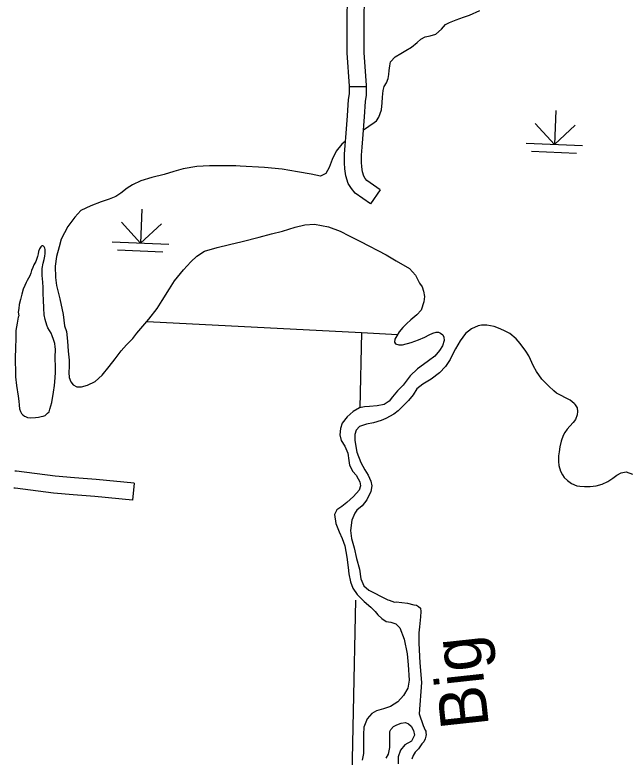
# Model space of a CAD drawing. Extents: x 1196286 to 1268366, y 2040822 to 2082115.
# Drawn here: x 1233530 to 1235560, y 2051997 to 2054453 of the extents above; entities that cross this region are included whole.
import ezdxf

# ---------------------------------------------------------------- set-up
doc = ezdxf.new("R2010")
doc.units = 0
for name, color, linetype in [('60', 7, 'Continuous'), ('62', 7, 'Continuous'), ('Level 69', 7, 'Continuous'), ('Level 73', 7, 'Continuous'), ('Level 74', 7, 'Continuous'), ('Level 86', 7, 'Continuous')]:
    doc.layers.add(name, color=color, linetype=linetype)

msp = doc.modelspace()

# ---------------------------------------------------------------- linework, layer by layer
at = {"layer": '60'}
for points in [[(1234677.4, 2053402.1), (1234672, 2053153)], [(1234658.3, 2052516.7), (1234634.4, 2051411.2)]]:
    msp.add_lwpolyline(points, dxfattribs=at)
at = {"layer": '62'}
for points in [[(1233540.8, 2053452.4), (1233537.6, 2053432.5), (1233533.5, 2053408.9), (1233533.5, 2053380.3), (1233532, 2053353.6), (1233530.8, 2053314.5), (1233531.3, 2053302.5), (1233531.8, 2053278.4), (1233531.8, 2053255.5), (1233535.2, 2053226.9), (1233540.7, 2053191.8), (1233543.5, 2053174.5), (1233544.4, 2053161.3), (1233546.1, 2053149.6), (1233549, 2053140.9), (1233552.7, 2053134.5), (1233556.3, 2053129.2), (1233562.3, 2053125.3), (1233565.3, 2053124.1), (1233572, 2053120.7), (1233580.6, 2053119.4), (1233598.9, 2053120.3), (1233608.3, 2053121.3), (1233617, 2053123.8), (1233623.7, 2053125.2), (1233630.5, 2053127.4), (1233638.8, 2053134.8), (1233643.4, 2053139.6), (1233646.1, 2053148.6), (1233652.4, 2053169.9), (1233657.8, 2053204.5), (1233661.4, 2053226.2), (1233664, 2053252.5), (1233664.7, 2053271.3), (1233664.5, 2053290.5), (1233663.4, 2053315), (1233663.9, 2053328.9), (1233664.4, 2053337.5), (1233664.5, 2053346.5), (1233663.9, 2053354.1), (1233662.6, 2053366.1), (1233658.6, 2053379.3), (1233653.5, 2053391.1), (1233650.3, 2053400.1), (1233639.3, 2053417.6), (1233636, 2053425.9), (1233631, 2053444.8), (1233627.1, 2053460.2), (1233626.3, 2053482.4), (1233624.8, 2053510.3), (1233623.9, 2053529.5), (1233623.9, 2053550.5), (1233623, 2053569), (1233620.7, 2053591.2), (1233621, 2053613.7), (1233624.2, 2053631.8), (1233627, 2053643.8), (1233629.4, 2053655), (1233630.3, 2053663.6), (1233630.7, 2053670.8), (1233630.4, 2053677.2), (1233629.4, 2053681.3), (1233626.8, 2053685.5), (1233625.3, 2053687.4), (1233623.1, 2053688.6), (1233621.6, 2053689.3), (1233619.4, 2053688.6), (1233615.9, 2053685.6), (1233611.7, 2053678.6), (1233609, 2053669.9), (1233607, 2053662.5), (1233605, 2053653.1), (1233603.1, 2053646.7), (1233599.6, 2053637.4), (1233593.4, 2053625.8), (1233589.2, 2053616.8), (1233585.7, 2053606.7), (1233582.9, 2053598.1), (1233579.8, 2053589.9), (1233571, 2053574.6), (1233567.9, 2053567.9), (1233562.9, 2053557.8), (1233557.5, 2053545.4), (1233552.8, 2053529), (1233548.4, 2053511.7), (1233544.8, 2053495.2), (1233543.1, 2053481), (1233541.7, 2053469.7), (1233542.9, 2053457.3), (1233540.8, 2053452.4)], [(1235381.5, 2053167.4), (1235368.6, 2053178.1), (1235323.5, 2053201.3), (1235314.6, 2053208.6), (1235297.2, 2053224.6), (1235274.7, 2053247.1), (1235257.4, 2053272.6), (1235247.5, 2053290.7), (1235231.9, 2053324.8), (1235222, 2053340.7), (1235202.8, 2053365.1), (1235190, 2053381), (1235168.1, 2053399), (1235153.6, 2053406.4), (1235136.5, 2053413.7), (1235117.1, 2053421.9), (1235092.4, 2053426), (1235074.8, 2053425.9), (1235063.9, 2053424.2), (1235041.3, 2053414.7), (1235021.6, 2053399.2), (1235003.7, 2053374.6), (1234988.7, 2053348.5), (1234978, 2053327.2), (1234970.6, 2053313), (1234955.7, 2053289.5), (1234936, 2053269.1), (1234908.3, 2053248.1), (1234880.8, 2053230.8), (1234861.1, 2053215.6), (1234848.1, 2053195.5), (1234833.6, 2053177.3), (1234812.3, 2053155.8), (1234798.7, 2053142.4), (1234785, 2053131.7), (1234758.2, 2053117.8), (1234742.4, 2053111.2), (1234717.2, 2053103.3), (1234694.7, 2053098.3), (1234671.3, 2053090.8), (1234660.3, 2053079.3), (1234655.3, 2053065), (1234655.4, 2053045.1), (1234662, 2053006.3), (1234675, 2052971.9), (1234688.5, 2052947.6), (1234699.9, 2052929.4), (1234708.6, 2052910.5), (1234712.1, 2052895), (1234708.5, 2052875.5), (1234695.4, 2052848.3), (1234679.8, 2052828.5), (1234662.7, 2052813.7), (1234655.1, 2052803.7), (1234645.8, 2052781.3), (1234641.2, 2052746.3), (1234644.6, 2052720.4), (1234653.9, 2052689.4), (1234660.9, 2052653.6), (1234670.6, 2052618.5), (1234675, 2052586.8), (1234685.6, 2052563.3), (1234701.8, 2052549.2), (1234720.1, 2052540.7), (1234742.8, 2052528), (1234764.3, 2052517.5), (1234769.6, 2052515.9), (1234786.7, 2052510), (1234792.7, 2052511.1), (1234829.4, 2052506.8), (1234850.7, 2052501.3), (1234859.2, 2052499.6), (1234866.7, 2052495.4), (1234872.6, 2052490.1), (1234873.9, 2052478.8), (1234872.6, 2052461.5), (1234869.1, 2052428.4), (1234867.7, 2052407.8), (1234866.9, 2052373.6), (1234870.9, 2052308.4), (1234876, 2052243.3), (1234868.2, 2052140.4), (1234882.3, 2052101.8), (1234888.9, 2052086), (1234890.7, 2052082.2), (1234891, 2052077.6), (1234891.3, 2052071.6), (1234890.5, 2052066.4), (1234888.8, 2052057.4), (1234884.2, 2052047.7), (1234877.8, 2052040.2), (1234866.3, 2052024.6), (1234855.7, 2052013.1), (1234848.8, 2052001.9), (1234843.7, 2051990.3)], [(1235381.5, 2053167.4), (1235385.1, 2053163), (1235391.5, 2053152.6), (1235392.5, 2053141.1), (1235391.9, 2053129.8), (1235386, 2053114.5), (1235378.7, 2053104.1), (1235367.6, 2053091.9), (1235358.4, 2053081.9), (1235350.3, 2053071.2), (1235345.2, 2053061.1), (1235338.9, 2053042.8), (1235334.4, 2053023.4), (1235331.8, 2053007.2), (1235329.7, 2052993.7), (1235329.7, 2052974.9), (1235330.9, 2052962.1), (1235336.5, 2052943.2), (1235342.7, 2052931), (1235348.5, 2052921.9), (1235359.2, 2052912.3), (1235372.8, 2052901.8), (1235389.9, 2052894.7), (1235400.8, 2052893), (1235415.4, 2052892), (1235434.5, 2052892.7), (1235454.8, 2052894.5), (1235474.4, 2052900.5), (1235492.9, 2052908.8), (1235509.2, 2052920.2), (1235522.9, 2052930), (1235537.3, 2052938), (1235553.5, 2052941.1), (1235574.3, 2052932.8)]]:
    msp.add_lwpolyline(points, dxfattribs=at)
at = {"layer": 'Level 69'}
for p, q in [((1234693.8, 2054215.6), (1234637.5, 2054214.9)), ((1234739.9, 2053874), (1234707.3, 2053828.2)), ((1233925.3, 2052903.5), (1233920, 2052847.5))]:
    msp.add_line(p, q, dxfattribs=at)
for points in [[(1234630.5, 2054413.1), (1234631.3, 2054535.2), (1234629.9, 2054610.4)], [(1234686.8, 2054412.8), (1234687.6, 2054535.5), (1234686.1, 2054611.5)], [(1234637.5, 2054214.9), (1234637.5, 2054217.1), (1234630, 2054327.3), (1234630.5, 2054413.1)], [(1234693.8, 2054215.6), (1234693.7, 2054219.4), (1234686.3, 2054329), (1234686.8, 2054412.8)], [(1234623.7, 2054020.6), (1234626.3, 2054047.5), (1234631.7, 2054119.5), (1234635.1, 2054172.7), (1234637.8, 2054191.5), (1234637.5, 2054214.9)], [(1234679.7, 2054015.2), (1234682.3, 2054042.6), (1234687.8, 2054115.6), (1234691.1, 2054166.9), (1234694.1, 2054187.8), (1234693.8, 2054215.6)], [(1234707.3, 2053828.2), (1234657.2, 2053863.7), (1234644.9, 2053878.5), (1234633.8, 2053895.7), (1234626, 2053920.9), (1234622.4, 2053943.8), (1234621, 2053964), (1234620.9, 2053991.9), (1234623.7, 2054020.6)], [(1234739.9, 2053874), (1234695.8, 2053905.3), (1234690.3, 2053911.9), (1234685.3, 2053919.7), (1234680.9, 2053933.8), (1234678.3, 2053950.1), (1234677.2, 2053966), (1234677.2, 2053989.3), (1234679.7, 2054015.2)], [(1233727.8, 2052921.4), (1233663.7, 2052926.7), (1233535.7, 2052943.2), (1233530.2, 2052943.5)], [(1233925.3, 2052903.5), (1233799.8, 2052915.4), (1233727.8, 2052921.4)], [(1233723.1, 2052865.3), (1233657.8, 2052870.7), (1233530.7, 2052887.1), (1233527.3, 2052887.3)], [(1233920, 2052847.5), (1233794.8, 2052859.4), (1233723.1, 2052865.3)]]:
    msp.add_lwpolyline(points, dxfattribs=at)
at = {"layer": 'Level 73'}
for p, q in [((1235320.8, 2054137.1), (1235316, 2054024.7)), ((1235316, 2054024.7), (1235252.6, 2054093.8)), ((1235316, 2054024.7), (1235385.1, 2054088.1)), ((1235222.3, 2054028.7), (1235409.7, 2054020.7)), ((1235240, 2054002.4), (1235389.8, 2053996)), ((1233951, 2053810.4), (1233946.2, 2053698)), ((1233946.2, 2053698), (1233882.8, 2053767.1)), ((1233946.2, 2053698), (1234015.3, 2053761.4)), ((1233852.5, 2053702.1), (1234039.9, 2053694)), ((1233870.2, 2053675.7), (1234020, 2053669.3))]:
    msp.add_line(p, q, dxfattribs=at)
at = {"layer": 'Level 74'}
for points in [[(1234684.6, 2054072.9), (1234719.6, 2054096.9), (1234726.8, 2054103.1), (1234735.3, 2054114.6), (1234743.6, 2054139.3), (1234746.3, 2054162.5), (1234747.5, 2054181.3), (1234749.8, 2054203.5), (1234753, 2054216.2), (1234760.8, 2054228.8), (1234766.3, 2054243), (1234768.1, 2054256.1), (1234768.7, 2054269.3), (1234770.9, 2054285), (1234774.1, 2054297.8), (1234789.4, 2054314.8), (1234807.7, 2054325.7), (1234824.3, 2054335.1), (1234842.9, 2054346), (1234862, 2054361.4), (1234873.8, 2054372.5), (1234888.2, 2054380.5), (1234905.1, 2054383.9), (1234923.2, 2054389.9), (1234941.9, 2054406.5), (1234955.7, 2054421.6), (1234968.6, 2054428.5), (1234990.9, 2054436.4), (1235015, 2054445.3), (1235035.4, 2054452.4), (1235069.8, 2054467.9)], [(1234625.1, 2054035.1), (1234612.8, 2054025.7), (1234594.2, 2054002.6), (1234580.7, 2053974.2), (1234571, 2053948.4), (1234559.1, 2053928.7), (1234542.1, 2053919.9), (1234511.5, 2053925.6), (1234466.2, 2053933.7), (1234414.7, 2053943.1), (1234356.7, 2053948), (1234276.2, 2053952.5), (1234261.6, 2053953.5), (1234217.8, 2053954.1), (1234174.7, 2053953.5), (1234133.1, 2053951.9), (1234087.3, 2053943.9), (1234056.5, 2053934.5), (1234024.5, 2053925.2), (1233983.2, 2053915.2), (1233947, 2053903.7), (1233919.9, 2053891.3), (1233902.1, 2053880.2), (1233880.9, 2053863.2), (1233863.9, 2053852.2), (1233842.1, 2053843.1), (1233816.1, 2053834.8), (1233781.5, 2053821.4), (1233748.3, 2053805.7), (1233728.9, 2053783.7), (1233705.6, 2053752.8), (1233683.7, 2053711.4), (1233677.4, 2053685.9), (1233668, 2053653.7), (1233664.1, 2053621.4), (1233664.8, 2053583.8), (1233667.8, 2053557.8), (1233679.2, 2053513.7), (1233690.5, 2053462), (1233694.4, 2053424), (1233700.9, 2053405.1), (1233704.2, 2053373.4), (1233707.2, 2053340.3), (1233709.8, 2053310.9), (1233710.2, 2053289.5), (1233709.2, 2053269.6), (1233709.7, 2053253.4), (1233715.2, 2053238.6), (1233723.3, 2053228.4), (1233735.2, 2053222.2), (1233750.5, 2053222.4), (1233770.8, 2053227.3), (1233795.7, 2053240.2), (1233819.2, 2053261.3), (1233842.1, 2053289.5), (1233861.9, 2053314.8), (1233881.7, 2053341.6), (1233899.6, 2053360.9), (1233920.9, 2053382.5)], [(1233920.9, 2053382.5), (1233933.8, 2053400), (1233973.4, 2053445.7), (1234000.9, 2053481), (1234017.3, 2053507.8), (1234042.2, 2053547), (1234058.7, 2053572.7), (1234088.8, 2053609.5), (1234112.7, 2053636.3), (1234132.1, 2053654.8), (1234157.4, 2053671), (1234200.3, 2053683.9), (1234241.2, 2053693.1), (1234282.9, 2053702.7), (1234339.3, 2053717.7), (1234379.6, 2053728.1), (1234415.6, 2053737.4), (1234457.8, 2053750.7), (1234490.5, 2053758.1), (1234522.3, 2053760.7), (1234568.7, 2053751.4), (1234607.4, 2053737.7), (1234637.2, 2053721.9), (1234674.4, 2053703.3), (1234759.6, 2053659.3), (1234792.6, 2053639.6), (1234836.5, 2053613.8), (1234856.8, 2053591.7), (1234869.9, 2053565.2), (1234878, 2053552.7), (1234883.1, 2053539.1), (1234886.2, 2053521), (1234884.4, 2053503), (1234874.7, 2053476.4), (1234861, 2053460.8), (1234840.9, 2053443.8), (1234826.5, 2053431.2), (1234814.4, 2053418.6), (1234802.6, 2053404.8), (1234794.5, 2053391.4), (1234787.6, 2053379.8), (1234787.1, 2053370.5), (1234789.7, 2053364.8), (1234801.6, 2053360.8), (1234813.2, 2053361.1), (1234841.8, 2053368.9), (1234865.9, 2053377.6), (1234887, 2053386.7), (1234901.7, 2053394.1), (1234914.1, 2053399.9), (1234924.7, 2053402.8), (1234932.2, 2053402.7), (1234939.6, 2053399.9), (1234947.4, 2053394.6), (1234950.3, 2053386.6), (1234951.6, 2053375.7), (1234945.4, 2053358.1), (1234936.2, 2053342.8), (1234920.6, 2053324.2), (1234899.4, 2053308.4), (1234882.8, 2053296.5), (1234863.1, 2053282.2), (1234838.8, 2053258.4), (1234815.5, 2053227.9), (1234797.3, 2053209), (1234780.6, 2053188.9), (1234768.8, 2053175.2), (1234752.5, 2053164.1), (1234729.6, 2053159.2), (1234703.7, 2053156.9), (1234687.2, 2053156), (1234671.1, 2053152.4), (1234650.3, 2053140.7), (1234629.8, 2053122.6), (1234613.4, 2053102.1), (1234607.6, 2053084.5), (1234605.4, 2053063.1), (1234610.8, 2053044.6), (1234622.1, 2053025.6), (1234631.9, 2053002.2), (1234636.1, 2052978.8), (1234638.2, 2052963.4), (1234649.1, 2052942.2), (1234659.8, 2052929.6), (1234667.1, 2052918.2), (1234672.2, 2052907.6), (1234674.3, 2052894.4), (1234670.4, 2052879.8), (1234650.6, 2052859), (1234629.4, 2052839.4), (1234612, 2052826.5), (1234595.7, 2052815.4), (1234588.7, 2052800.1), (1234592.8, 2052770.3), (1234603.7, 2052742.7), (1234613.5, 2052720), (1234622.2, 2052696.2), (1234629.2, 2052658.9), (1234633.9, 2052623.9), (1234635.5, 2052603.1), (1234641.2, 2052576.7)], [(1234641.2, 2052576.7), (1234648.7, 2052556.3), (1234663.8, 2052535.4), (1234686.4, 2052512.2), (1234708.2, 2052492.7), (1234723.4, 2052479), (1234732.2, 2052467.2), (1234745.1, 2052455), (1234758.9, 2052446.1), (1234774.2, 2052443.3), (1234791.7, 2052437.8), (1234804.7, 2052424.8), (1234818.4, 2052387.4), (1234828.6, 2052338.4), (1234832.6, 2052301.8), (1234834.9, 2052251.4), (1234831.2, 2052225.5), (1234816.6, 2052200.5), (1234798, 2052179.7), (1234773.8, 2052163.9), (1234750.1, 2052156.7), (1234727.5, 2052150.2), (1234711.3, 2052141.4), (1234696.5, 2052123.2), (1234685.2, 2052096.3), (1234683.8, 2052071.5), (1234683.7, 2052039.2), (1234684.4, 2052009.1), (1234680, 2051986.2)], [(1234758.8, 2051993.7), (1234766.8, 2052006.8), (1234771.6, 2052028.5), (1234771.1, 2052044.7), (1234771.3, 2052065), (1234771.5, 2052074), (1234771.2, 2052081.2), (1234774.3, 2052088.7), (1234783.8, 2052097.9), (1234794.3, 2052103.4), (1234808.6, 2052109.3), (1234823.6, 2052110.9), (1234833, 2052107), (1234841.5, 2052099), (1234849.9, 2052085), (1234853.1, 2052069.5), (1234843.4, 2052049.7), (1234821.1, 2052037.3), (1234806.7, 2052019.4), (1234799.3, 2051997.3), (1234798.6, 2051974)]]:
    msp.add_lwpolyline(points, dxfattribs=at)
at = {"layer": 'Level 86'}
for points in [[(1233968.1, 2053438.8), (1234677.4, 2053402.1)], [(1234677.4, 2053402.1), (1234796.8, 2053395.2)]]:
    msp.add_lwpolyline(points, dxfattribs=at)

# ---------------------------------------------------------------- texts
at = {"layer": '62'}
msp.add_text('Big', height=158.4, rotation=96.2119, dxfattribs=at).set_placement((1235099.8, 2052099.8))

doc.saveas('drawing.dxf')
